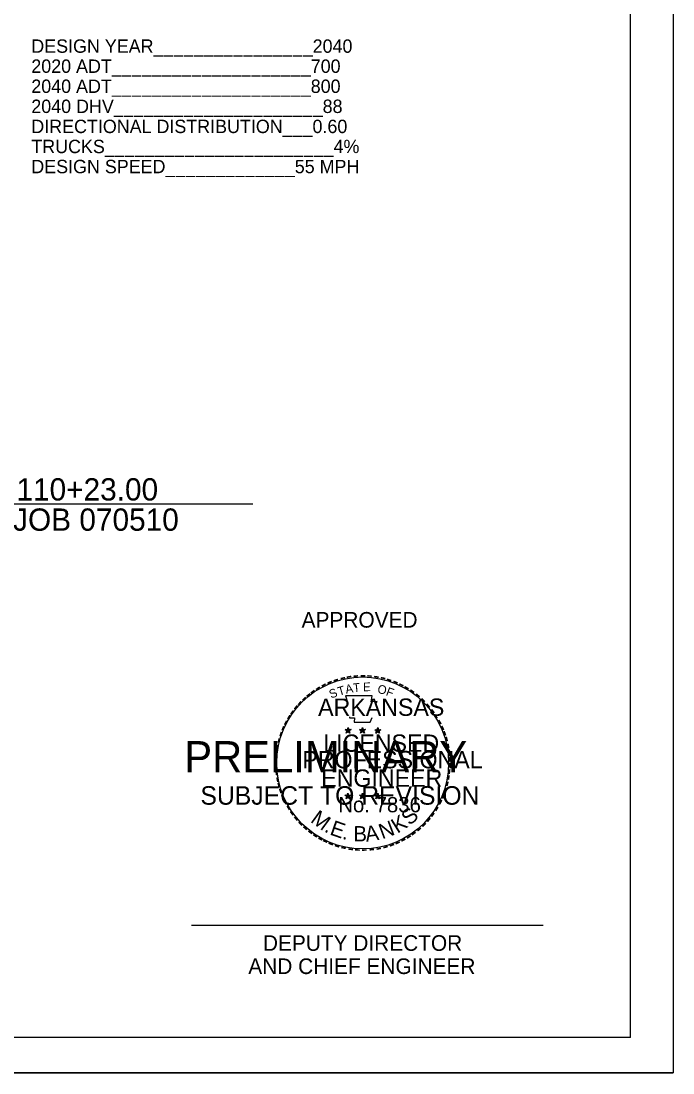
# Model space of a CAD drawing. Extents: x 1373094 to 1376427, y 1168361 to 1170494.
# Drawn here: x 1375696 to 1376427, y 1168361 to 1169540 of the extents above; entities that cross this region are included whole.
import ezdxf

# ---------------------------------------------------------------- set-up
doc = ezdxf.new("R2010")
doc.units = 0
for name, color, linetype in [('R_Border', 7, 'Continuous'), ('R_Border PE', 7, 'Continuous'), ('R_Border Prem', 7, 'Continuous'), ('R_Dimension', 7, 'Continuous'), ('R_Draft', 7, 'Continuous'), ('R_No Plot', 7, 'Continuous')]:
    doc.layers.add(name, color=color, linetype=linetype)

msp = doc.modelspace()

# ---------------------------------------------------------------- linework, layer by layer
at = {"layer": 'R_Border'}
for q in [(1376379.5, 1170455.4), (1373217.7, 1168400.8)]:
    msp.add_line((1376379.5, 1168400.8), q, dxfattribs=at)
at = {"layer": 'R_Border PE'}
for p, q in [((1376062.6, 1168748.4), (1376062.2, 1168745.9)), ((1376062.6, 1168744.8), (1376062.6, 1168748.4)), ((1376062.6, 1168748.4), (1376063.1, 1168746)), ((1376078.9, 1168748.4), (1376078.5, 1168745.9)), ((1376078.9, 1168744.8), (1376078.9, 1168748.4)), ((1376078.9, 1168748.4), (1376079.3, 1168746)), ((1376096, 1168748.2), (1376095.6, 1168745.8)), ((1376096, 1168744.7), (1376096, 1168748.2)), ((1376096, 1168748.2), (1376096.4, 1168745.8)), ((1376059.2, 1168745.9), (1376062.6, 1168744.8)), ((1376059.2, 1168745.9), (1376061.7, 1168745.5)), ((1376059.2, 1168745.9), (1376061.5, 1168744.7)), ((1376060.5, 1168741.9), (1376062.6, 1168744.8)), ((1376060.5, 1168741.9), (1376061.7, 1168744.3)), ((1376060.5, 1168741.9), (1376062.5, 1168744)), ((1376064.7, 1168741.9), (1376062.5, 1168744)), ((1376065.9, 1168745.9), (1376062.6, 1168744.8)), ((1376064.7, 1168741.9), (1376062.6, 1168744.8)), ((1376065.9, 1168745.9), (1376063.2, 1168745.4)), ((1376064.7, 1168741.9), (1376063.3, 1168744.7)), ((1376065.9, 1168745.9), (1376064, 1168744.9)), ((1376075.5, 1168745.9), (1376078.9, 1168744.8)), ((1376075.5, 1168745.9), (1376077.9, 1168745.5)), ((1376075.5, 1168745.9), (1376077.7, 1168744.7)), ((1376076.7, 1168741.9), (1376078.9, 1168744.8)), ((1376076.7, 1168741.9), (1376078, 1168744.3)), ((1376076.7, 1168741.9), (1376078.8, 1168744)), ((1376080.9, 1168741.9), (1376078.8, 1168744)), ((1376082.2, 1168745.9), (1376078.9, 1168744.8)), ((1376080.9, 1168741.9), (1376078.9, 1168744.8)), ((1376082.2, 1168745.9), (1376079.4, 1168745.4)), ((1376080.9, 1168741.9), (1376079.5, 1168744.7)), ((1376082.2, 1168745.9), (1376080.2, 1168744.9)), ((1376092.6, 1168745.8), (1376096, 1168744.7)), ((1376092.6, 1168745.8), (1376095, 1168745.3)), ((1376092.6, 1168745.8), (1376094.9, 1168744.6)), ((1376093.8, 1168741.8), (1376096, 1168744.7)), ((1376093.8, 1168741.8), (1376095.1, 1168744.2)), ((1376093.8, 1168741.8), (1376096, 1168743.9)), ((1376099.4, 1168745.8), (1376096, 1168744.7)), ((1376098, 1168741.8), (1376096, 1168744.7)), ((1376098, 1168741.8), (1376096, 1168743.9)), ((1376099.4, 1168745.8), (1376096.5, 1168745.3)), ((1376098, 1168741.8), (1376096.7, 1168744.6)), ((1376099.4, 1168745.8), (1376097.3, 1168744.8)), ((1376059.1, 1168672.3), (1376062.5, 1168671.2)), ((1376059.1, 1168672.3), (1376061.7, 1168671.8)), ((1376059.1, 1168672.3), (1376061.5, 1168671.1)), ((1376060.5, 1168668.3), (1376062.5, 1168671.2)), ((1376060.5, 1168668.3), (1376061.7, 1168670.7)), ((1376060.5, 1168668.3), (1376062.5, 1168670.5)), ((1376062.5, 1168674.7), (1376062.1, 1168672.3)), ((1376062.5, 1168671.2), (1376062.5, 1168674.7)), ((1376062.5, 1168674.7), (1376063, 1168672.3)), ((1376065.9, 1168672.3), (1376062.5, 1168671.2)), ((1376064.7, 1168668.3), (1376062.5, 1168671.2)), ((1376064.7, 1168668.3), (1376062.5, 1168670.4)), ((1376065.9, 1168672.3), (1376063.1, 1168671.8)), ((1376064.7, 1168668.3), (1376063.3, 1168671.1)), ((1376065.9, 1168672.3), (1376064, 1168671.3)), ((1376075.4, 1168672.3), (1376078.8, 1168671.2)), ((1376075.4, 1168672.3), (1376077.9, 1168671.8)), ((1376075.4, 1168672.3), (1376077.7, 1168671.1)), ((1376076.7, 1168668.3), (1376078.8, 1168671.2)), ((1376076.7, 1168668.3), (1376077.9, 1168670.7)), ((1376076.7, 1168668.3), (1376078.8, 1168670.5)), ((1376078.8, 1168674.7), (1376078.4, 1168672.3)), ((1376078.8, 1168671.2), (1376078.8, 1168674.7)), ((1376078.8, 1168674.7), (1376079.2, 1168672.3)), ((1376082.2, 1168672.3), (1376078.8, 1168671.2)), ((1376080.8, 1168668.3), (1376078.8, 1168671.2)), ((1376080.8, 1168668.3), (1376078.8, 1168670.4)), ((1376082.2, 1168672.3), (1376079.3, 1168671.8)), ((1376080.8, 1168668.3), (1376079.5, 1168671.1)), ((1376082.2, 1168672.3), (1376080.1, 1168671.3)), ((1376092.6, 1168672.2), (1376096, 1168671.1)), ((1376092.6, 1168672.2), (1376095, 1168671.7)), ((1376092.6, 1168672.2), (1376094.9, 1168671)), ((1376093.8, 1168668.2), (1376096, 1168671.1)), ((1376093.8, 1168668.2), (1376095.1, 1168670.6)), ((1376093.8, 1168668.2), (1376096, 1168670.4)), ((1376096, 1168674.6), (1376095.6, 1168672.2)), ((1376096, 1168671.1), (1376096, 1168674.6)), ((1376096, 1168674.6), (1376096.4, 1168672.2)), ((1376099.4, 1168672.2), (1376096, 1168671.1)), ((1376098, 1168668.2), (1376096, 1168671.1)), ((1376098, 1168668.2), (1376096, 1168670.3)), ((1376099.4, 1168672.2), (1376096.5, 1168671.7)), ((1376098, 1168668.2), (1376096.6, 1168671)), ((1376099.4, 1168672.2), (1376097.3, 1168671.2)), ((1375886.9, 1168526.6), (1376281.3, 1168526.6))]:
    msp.add_line(p, q, dxfattribs=at)
for points in [[(1376059.6, 1168783.6), (1376062.2, 1168775.5)], [(1376093.7, 1168774.7), (1376095.1, 1168777.4), (1376088.5, 1168777.2), (1376089.8, 1168783.6), (1376059.6, 1168783.6)], [(1376064.4, 1168760.1), (1376064.4, 1168759.2), (1376069.8, 1168759), (1376069.3, 1168754.4), (1376087.5, 1168754.4), (1376089.5, 1168759.6)], [(1376062.6, 1168748.4), (1376064.7, 1168741.9), (1376059.2, 1168745.9), (1376065.9, 1168745.9), (1376060.5, 1168741.9), (1376062.6, 1168748.4)], [(1376078.9, 1168748.4), (1376080.9, 1168741.9), (1376075.5, 1168745.9), (1376082.2, 1168745.9), (1376076.7, 1168741.9), (1376078.9, 1168748.4)], [(1376096, 1168748.2), (1376098, 1168741.8), (1376092.6, 1168745.8), (1376099.4, 1168745.8), (1376093.8, 1168741.8), (1376096, 1168748.2)], [(1376062.5, 1168674.7), (1376064.7, 1168668.3), (1376059.1, 1168672.3), (1376065.9, 1168672.3), (1376060.5, 1168668.3), (1376062.5, 1168674.7)], [(1376078.8, 1168674.7), (1376080.8, 1168668.3), (1376075.4, 1168672.3), (1376082.2, 1168672.3), (1376076.7, 1168668.3), (1376078.8, 1168674.7)], [(1376096, 1168674.6), (1376098, 1168668.2), (1376092.6, 1168672.2), (1376099.4, 1168672.2), (1376093.8, 1168668.2), (1376096, 1168674.6)]]:
    msp.add_lwpolyline(points, dxfattribs=at)
for centre, radius in [((1376079, 1168708.5), 96.4), ((1376062.5, 1168744.8), 1.67), ((1376062.5, 1168744.8), 1.41), ((1376062.5, 1168744.8), 1.13), ((1376062.5, 1168744.8), 0.963), ((1376062.5, 1168744.8), 0.726), ((1376062.5, 1168744.8), 0.482), ((1376062.5, 1168744.8), 0.288), ((1376078.8, 1168744.8), 1.67), ((1376078.8, 1168744.8), 1.41), ((1376078.8, 1168744.8), 1.13), ((1376078.8, 1168744.8), 0.963), ((1376078.8, 1168744.8), 0.726), ((1376078.8, 1168744.8), 0.482), ((1376078.8, 1168744.8), 0.288), ((1376095.9, 1168744.7), 1.67), ((1376095.9, 1168744.7), 1.41), ((1376095.9, 1168744.7), 1.13), ((1376095.9, 1168744.7), 0.963), ((1376095.9, 1168744.7), 0.726), ((1376095.9, 1168744.7), 0.482), ((1376095.9, 1168744.7), 0.288), ((1376062.5, 1168671.2), 1.67), ((1376062.5, 1168671.2), 1.41), ((1376062.5, 1168671.2), 1.13), ((1376062.5, 1168671.2), 0.963), ((1376062.5, 1168671.2), 0.726), ((1376062.5, 1168671.2), 0.482), ((1376062.5, 1168671.2), 0.288), ((1376078.7, 1168671.2), 1.67), ((1376078.7, 1168671.2), 1.41), ((1376078.7, 1168671.2), 1.13), ((1376078.7, 1168671.2), 0.963), ((1376078.7, 1168671.2), 0.726), ((1376078.7, 1168671.2), 0.482), ((1376078.7, 1168671.2), 0.288), ((1376095.9, 1168671.1), 1.67), ((1376095.9, 1168671.1), 1.41), ((1376095.9, 1168671.1), 1.13), ((1376095.9, 1168671.1), 0.963), ((1376095.9, 1168671.1), 0.726), ((1376095.9, 1168671.1), 0.482), ((1376095.9, 1168671.1), 0.288)]:
    msp.add_circle(centre, radius, dxfattribs=at)
at = {"layer": 'R_Dimension'}
msp.add_line((1375607, 1168998.8), (1375955.8, 1168998.8), dxfattribs=at)
at = {"layer": 'R_No Plot'}
msp.add_line((1373093.7, 1168361), (1376427.1, 1168361), dxfattribs=at)
msp.add_lwpolyline([(1373093.7, 1170494.4), (1376427.1, 1170494.4), (1376427.1, 1168361), (1373093.7, 1168361)], close=True, dxfattribs=at)

# ---------------------------------------------------------------- texts
at = {"layer": 'R_Border PE'}
for s, height, p in [('APPROVED', 17.5, (1376010.5, 1168860.2)), ('ARKANSAS', 19.44, (1376029, 1168761.3)), ('LICENSED', 19.44, (1376034.8, 1168721)), ('PROFESSIONAL', 19.44, (1376011.3, 1168702.5)), ('ENGINEER', 19.44, (1376032.5, 1168681.8)), ('No. 7836', 17.08, (1376051.6, 1168653.2)), ('DEPUTY DIRECTOR', 17.496, (1375967.1, 1168497.9)), ('AND CHIEF ENGINEER', 17.496, (1375950.7, 1168471.9))]:
    msp.add_text(s, height=height, dxfattribs=at).set_placement(p)
for s, height, rotation, p in [('-', 15.6, 10.2193, (1376061.3, 1168798.5)), ('-', 15.6, 5.8968, (1376068.4, 1168799.5)), ('-', 15.6, 0.1862, (1376075.9, 1168800.2)), ('-', 15.6, 357.743, (1376082.9, 1168800.1)), ('-', 15.6, 352.1617, (1376090.1, 1168799.5)), ('-', 15.6, 34.0636, (1376029.3, 1168785.3)), ('-', 15.6, 28.7918, (1376035.1, 1168788.9)), ('-', 15.6, 24.3072, (1376041.2, 1168792)), ('-', 15.6, 19.1761, (1376047.5, 1168794.6)), ('T', 9.72, 16.4036, (1376052.5, 1168783.7)), ('-', 15.6, 13.6301, (1376054.8, 1168796.9)), ('A', 9.72, 11.2132, (1376060.5, 1168786.1)), ('T', 9.72, 6.0228, (1376068.7, 1168787.8)), ('E', 9.72, 0.8323, (1376079.5, 1168788.9)), ('O', 9.72, 350.4515, (1376095.1, 1168786.8)), ('-', 15.6, 347.2049, (1376097.1, 1168798.5)), ('-', 15.6, 342.3362, (1376103.4, 1168796.9)), ('-', 15.6, 337.8551, (1376110.4, 1168794.8)), ('-', 15.6, 334.1211, (1376116.6, 1168792.2)), ('-', 15.6, 329.6409, (1376122.2, 1168789.4)), ('-', 15.6, 42.9622, (1376014.9, 1168773.7)), ('-', 15.6, 38.9507, (1376019.1, 1168777.8)), ('-', 15.6, 36.2317, (1376023.6, 1168781.5)), ('S', 9.72, 21.594, (1376043.6, 1168780.5)), ('F', 9.72, 340.0707, (1376104.4, 1168784.6)), ('-', 15.6, 325.8627, (1376128.4, 1168785.9)), ('-', 15.6, 320.5297, (1376134.4, 1168781.8)), ('-', 15.6, 50.6142, (1376006.5, 1168764.4)), ('-', 15.6, 48.4231, (1376010.5, 1168769)), ('-', 15.6, 315.5786, (1376140.2, 1168777)), ('-', 15.6, 309.8797, (1376145.7, 1168771.6)), ('-', 15.6, 58.0706, (1375999.4, 1168753.7)), ('-', 15.6, 54.2325, (1376002.6, 1168758.8)), ('-', 15.6, 306.6522, (1376150.9, 1168765.8)), ('-', 13.6, 303.6753, (1376155.5, 1168760.3)), ('-', 15.6, 67.7743, (1375993.8, 1168741.8)), ('-', 15.6, 62.8713, (1375996.3, 1168747.7)), ('-', 15.6, 299.6684, (1376158.7, 1168754.3)), ('-', 15.6, 294.6628, (1376161.9, 1168748.4)), ('-', 15.6, 75.461, (1375989.8, 1168728.7)), ('-', 15.6, 72.3945, (1375991.8, 1168735.7)), ('-', 15.6, 290.5728, (1376164.3, 1168742.9)), ('-', 15.6, 285.1233, (1376166.6, 1168737.2)), ('-', 15.6, 81.2013, (1375988.6, 1168721.8)), ('-', 15.6, 280.5493, (1376168.6, 1168729.9)), ('-', 15.6, 89.0622, (1375987.6, 1168708.3)), ('-', 15.6, 85.1863, (1375987.8, 1168715.1)), ('-', 15.6, 276.5962, (1376170.1, 1168722.6)), ('-', 15.6, 274.3301, (1376170.7, 1168715.5)), ('-', 15.6, 94.1959, (1375987.9, 1168701.2)), ('-', 15.6, 98.9479, (1375988.6, 1168694.8)), ('-', 15.6, 263.5172, (1376170.8, 1168702.9)), ('-', 15.6, 269.9407, (1376171, 1168709.3)), ('-', 15.6, 101.7149, (1375989.9, 1168687.6)), ('-', 15.6, 255.7626, (1376169.1, 1168689.9)), ('-', 15.6, 260.9953, (1376170.1, 1168696.5)), ('-', 15.6, 105.4578, (1375991.5, 1168681.8)), ('-', 15.6, 109.0874, (1375993.5, 1168675.7)), ('-', 15.6, 252.8681, (1376167.3, 1168682.9)), ('-', 15.6, 114.0643, (1375996, 1168669.9)), ('-', 15.6, 115.7289, (1375999, 1168663.9)), ('-', 15.6, 244.6197, (1376162.6, 1168670.3)), ('-', 15.6, 247.8887, (1376165.2, 1168676.4)), ('-', 15.6, 120.4471, (1376002.5, 1168658.2)), ('-', 15.6, 125.8934, (1376006.3, 1168652.8)), ('M', 17.1, 323.9056, (1376019.5, 1168643)), ('S', 17.1, 42.9205, (1376131.9, 1168637.6)), ('-', 15.6, 233.8452, (1376154.9, 1168656.7)), ('-', 15.6, 239.0712, (1376158.8, 1168663)), ('-', 15.6, 130.7181, (1376010.9, 1168647.3)), ('-', 15.6, 134.2238, (1376015.9, 1168642.1)), ('E', 17.1, 340.8881, (1376041.2, 1168628.5)), ('N', 17.1, 20.5042, (1376100.9, 1168622.8)), ('K', 17.1, 32.2382, (1376117.9, 1168629)), ('-', 15.6, 225.7653, (1376146, 1168645.7)), ('-', 15.6, 231.2538, (1376150.7, 1168651.1)), ('-', 15.6, 138.9338, (1376021, 1168637.6)), ('-', 15.6, 144.6463, (1376026.4, 1168633.6)), ('-', 15.6, 148.0898, (1376031.8, 1168630)), ('.', 17.1, 336.3407, (1376035, 1168631.8)), ('B', 17.1, 359.3149, (1376068.5, 1168620.7)), ('A', 17.1, 8.7702, (1376083, 1168620.1)), ('-', 15.6, 215.7363, (1376135.6, 1168636.2)), ('-', 15.6, 221.0851, (1376141, 1168640.7)), ('-', 15.6, 151.5704, (1376037.4, 1168626.8)), ('-', 15.6, 154.6002, (1376042.6, 1168624.5)), ('-', 15.6, 158.5612, (1376048.6, 1168622)), ('-', 15.6, 162.7983, (1376055.3, 1168619.9)), ('.', 17.1, 350.694, (1376055.4, 1168623.2)), ('-', 15.6, 200.7184, (1376113, 1168623.2)), ('-', 15.6, 204.2516, (1376119, 1168625.8)), ('-', 15.6, 207.3568, (1376125, 1168629)), ('-', 15.6, 212.2491, (1376130.5, 1168632.4)), ('-', 15.6, 167.5555, (1376062.2, 1168618.4)), ('-', 15.6, 173.1155, (1376069.7, 1168617.3)), ('-', 15.6, 176.5183, (1376076.8, 1168616.8)), ('-', 15.6, 181.5918, (1376084.1, 1168617)), ('-', 15.6, 185.8167, (1376092.1, 1168617.7)), ('-', 15.6, 191.2858, (1376099.3, 1168618.9)), ('-', 15.6, 195.4743, (1376106.4, 1168620.9))]:
    msp.add_text(s, height=height, rotation=rotation, dxfattribs=at).set_placement(p)
at = {"layer": 'R_Border Prem'}
for s, height, p in [('PRELIMINARY', 35, (1375878.9, 1168698)), ('SUBJECT TO REVISION', 20.751, (1375897, 1168661.7))]:
    msp.add_text(s, height=height, dxfattribs=at).set_placement(p)
at = {"layer": 'R_Dimension'}
for s, p in [('STA. 110+23.00', (1375607, 1169002.7)), ('END JOB 070510', (1375607, 1168968.8))]:
    msp.add_text(s, height=25, rotation=0.0006, dxfattribs=at).set_placement(p)
at = {"layer": 'R_Draft'}
for s, p in [('DESIGN YEAR________________2040', (1375707.3, 1169504.6)), ('2020 ADT____________________700', (1375707.3, 1169482.1)), ('2040 ADT____________________800', (1375707.3, 1169459.6)), ('2040 DHV_____________________88', (1375707.3, 1169437.1)), ('DIRECTIONAL DISTRIBUTION___0.60', (1375707.3, 1169414.6)), ('TRUCKS_______________________4%', (1375707.3, 1169392.1)), ('DESIGN SPEED_____________55 MPH', (1375707.3, 1169369.6))]:
    msp.add_text(s, height=15, dxfattribs=at).set_placement(p)

doc.saveas('drawing.dxf')
